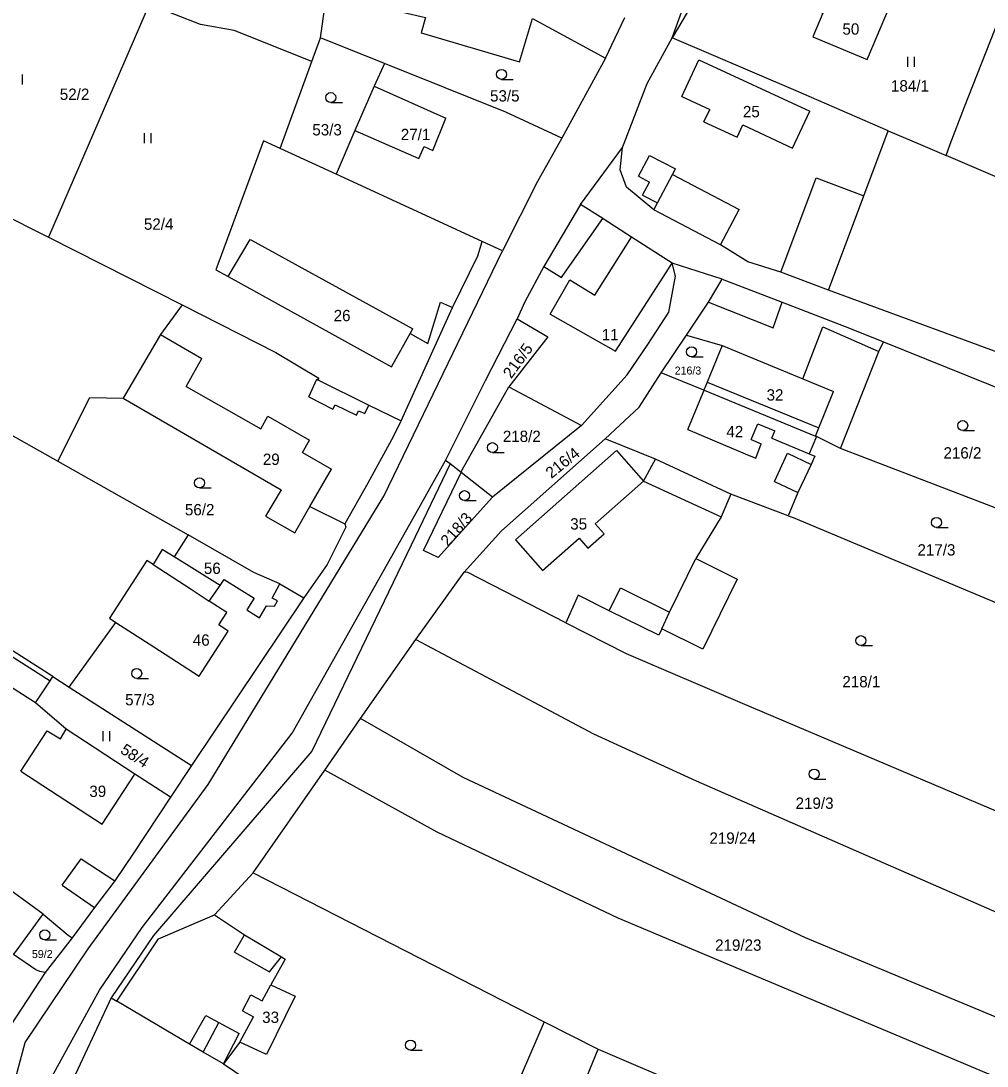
# Model space of a CAD drawing. Extents: x -744566 to -741843, y -1128407 to -1126744.
# Drawn here: x -743048.6 to -742903.8, y -1127701.7 to -1127545.1 of the extents above; entities that cross this region are included whole.
import ezdxf

# ---------------------------------------------------------------- set-up
doc = ezdxf.new("R2010")
doc.units = 0
for name, color, linetype in [('Hranice parcel', 7, 'Continuous'), ('Parcelní čísla', 7, 'Continuous'), ('Vnitřní kresba', 7, 'Continuous'), ('Značky kultur', 7, 'Continuous')]:
    doc.layers.add(name, color=color, linetype=linetype)

msp = doc.modelspace()

# ---------------------------------------------------------------- linework, layer by layer
at = {"layer": 'Hranice parcel'}
for p, q in [((-742950.97, -1127547.61), (-742944.28, -1127528.98)), ((-743029.41, -1127542.64), (-743044.5, -1127577.53)), ((-743003.69, -1127547.61), (-743002.99, -1127542.69)), ((-742960.97, -1127550.69), (-742958.07, -1127544.59)), ((-743005.01, -1127551.2), (-743003.69, -1127547.61)), ((-742994.1, -1127551.47), (-743003.69, -1127547.61)), ((-743009.74, -1127564.2), (-743005.01, -1127551.2)), ((-742960.97, -1127550.69), (-742967.51, -1127562.65)), ((-743001.38, -1127568.05), (-743009.74, -1127564.2)), ((-742964.75, -1127572.6), (-742958.43, -1127564.08)), ((-743067.95, -1127565.66), (-743044.5, -1127577.53)), ((-742979.47, -1127578.16), (-743001.38, -1127568.05)), ((-743044.5, -1127577.53), (-743024.44, -1127587.67)), ((-742943.48, -1127583.82), (-742951.01, -1127581.4)), ((-742985.72, -1127587.27), (-742983.9, -1127588.07)), ((-743082.43, -1127588.87), (-743043.08, -1127611.1)), ((-742991.6, -1127605.04), (-742983.9, -1127588.07)), ((-742952.62, -1127597.82), (-742948.85, -1127592.21)), ((-742919.33, -1127593.19), (-742889.07, -1127605.41)), ((-742946.24, -1127600.44), (-742952.62, -1127597.82)), ((-742982.46, -1127612.4), (-742975.48, -1127599.94)), ((-742975.48, -1127599.94), (-742964.56, -1127605.74)), ((-742964.56, -1127605.74), (-742977.94, -1127616.47)), ((-742925.74, -1127609.17), (-742929.36, -1127607.37)), ((-742892.31, -1127622.04), (-742925.74, -1127609.17)), ((-743043.08, -1127611.1), (-743023.57, -1127622.12)), ((-742982.64, -1127612.78), (-742984.29, -1127611.5)), ((-742982.64, -1127612.78), (-742982.46, -1127612.4)), ((-742977.94, -1127616.47), (-742982.64, -1127612.78)), ((-742933.59, -1127619.25), (-742942.21, -1127616.04)), ((-743023.57, -1127622.12), (-743025.65, -1127625.44)), ((-743029.73, -1127625.98), (-743035.35, -1127634.62)), ((-743018.73, -1127629.7), (-743025.65, -1127625.44)), ((-742989.43, -1127637.82), (-742982.16, -1127627.73)), ((-743009.79, -1127629.49), (-743006.21, -1127631.58)), ((-743006.21, -1127631.58), (-743023.07, -1127656.68)), ((-743041.39, -1127644.94), (-743034.37, -1127635.25)), ((-743035.35, -1127634.62), (-743034.37, -1127635.25)), ((-743043.83, -1127643.37), (-743054.68, -1127636.42)), ((-742997.69, -1127649.67), (-742989.43, -1127637.82)), ((-743046.41, -1127647.29), (-743053.43, -1127642.86)), ((-743043.83, -1127643.37), (-743041.39, -1127644.94)), ((-743041.39, -1127644.94), (-743023.07, -1127656.68)), ((-743003.07, -1127657.38), (-742997.69, -1127649.67)), ((-743023.07, -1127656.68), (-743026.2, -1127661.44)), ((-743013.81, -1127672.8), (-743003.07, -1127657.38)), ((-743045.29, -1127678.95), (-743062.24, -1127666.73)), ((-743019.62, -1127679.08), (-743013.81, -1127672.8)), ((-743013.81, -1127672.8), (-742970.18, -1127695.1)), ((-743040.96, -1127682.5), (-743044.97, -1127687.73)), ((-743044.97, -1127687.73), (-743050.26, -1127695.79)), ((-743035.1, -1127691.53), (-743041.92, -1127706.05)), ((-743035.1, -1127691.53), (-743034.24, -1127692.03)), ((-742970.18, -1127695.1), (-742980.63, -1127719.3)), ((-742970.18, -1127695.1), (-742962.09, -1127699.23)), ((-742972.01, -1127723.11), (-742962.09, -1127699.23)), ((-742962.09, -1127699.23), (-742911.19, -1127720.85))]:
    msp.add_line(p, q, dxfattribs=at)
for points in [[(-742942.64, -1127536.81), (-742945.7, -1127538.65), (-742950.97, -1127547.61)], [(-742925.16, -1127536.21), (-742926.91, -1127540.37), (-742928.31, -1127539.78), (-742929.81, -1127543.36), (-742928.41, -1127543.95), (-742929.89, -1127547.48), (-742921.76, -1127550.89), (-742917.03, -1127539.62), (-742925.16, -1127536.21)], [(-743005.01, -1127551.2), (-743016.66, -1127546.56), (-743021.68, -1127545.63), (-743029.41, -1127542.64)], [(-743002.99, -1127542.69), (-742991.4, -1127543.81), (-742987.95, -1127544.57), (-742988.63, -1127546.87), (-742973.89, -1127551.23), (-742971.94, -1127544.76), (-742960.97, -1127550.69)], [(-742909.93, -1127565.28), (-742909.31, -1127563.59), (-742907.18, -1127557.98), (-742901.31, -1127543.14)], [(-742958.43, -1127564.08), (-742954.72, -1127554.49), (-742950.97, -1127547.61)], [(-742918.6, -1127561.55), (-742932.41, -1127555.57), (-742950.97, -1127547.61)], [(-742994.1, -1127551.47), (-742995.64, -1127554.9), (-742998.58, -1127561.51), (-743001.38, -1127568.05)], [(-742967.51, -1127562.65), (-742975.9, -1127558.78), (-742994.1, -1127551.47)], [(-742927.53, -1127585.44), (-742922.25, -1127571.32), (-742918.6, -1127561.55)], [(-742918.6, -1127561.55), (-742913.78, -1127563.64), (-742909.93, -1127565.28)], [(-743009.74, -1127564.2), (-743012.24, -1127563.05), (-743019.38, -1127582.4), (-743017.56, -1127583.41), (-742993.08, -1127596.96), (-742990.26, -1127591.96)], [(-742967.51, -1127562.65), (-742971.19, -1127569.17), (-742976.43, -1127579.56), (-742979.47, -1127578.16)], [(-742927.53, -1127585.44), (-742934.7, -1127582.76), (-742939.64, -1127581.23), (-742943.72, -1127578.66), (-742953.72, -1127573.43), (-742957.84, -1127570.04), (-742958.76, -1127567.42), (-742958.43, -1127564.08)], [(-742851.05, -1127590.28), (-742889.01, -1127574.21), (-742909.93, -1127565.28)], [(-742964.75, -1127572.6), (-742970.21, -1127581.92), (-742973.05, -1127587.2), (-742974.2, -1127589.77)], [(-742951.01, -1127581.4), (-742957.06, -1127577.5), (-742961.32, -1127574.78), (-742961.39, -1127574.71), (-742964.75, -1127572.6)], [(-742983.9, -1127588.07), (-742980.12, -1127580.33), (-742979.47, -1127578.16)], [(-742964.56, -1127605.74), (-742957.73, -1127598.16), (-742954.62, -1127593.61), (-742951.47, -1127588.73), (-742950.51, -1127583.33), (-742951.01, -1127581.4)], [(-742948.85, -1127592.21), (-742945.53, -1127587.26), (-742943.48, -1127583.82)], [(-742943.48, -1127583.82), (-742934.51, -1127587.27), (-742924.42, -1127591.13), (-742919.33, -1127593.19)], [(-742885.79, -1127600.64), (-742896.8, -1127596.74), (-742927.53, -1127585.44)], [(-742990.26, -1127591.96), (-742987.63, -1127593.44), (-742985.72, -1127587.27)], [(-743024.44, -1127587.67), (-743027.7, -1127592.11), (-743033.28, -1127601.65)], [(-743024.44, -1127587.67), (-743010.42, -1127594.79), (-743003.98, -1127598.66), (-743004.09, -1127598.89), (-742996.47, -1127602.7), (-742991.6, -1127605.04)], [(-742984.29, -1127611.5), (-742984.97, -1127610.98), (-742978.95, -1127598.97), (-742974.2, -1127589.77)], [(-742974.2, -1127589.77), (-742969.61, -1127592.47), (-742975.48, -1127599.94)], [(-742948.85, -1127592.21), (-742943.5, -1127593.76), (-742945.74, -1127599.22), (-742946.24, -1127600.44)], [(-742925.74, -1127609.17), (-742920.01, -1127594.66), (-742919.33, -1127593.19)], [(-742961.05, -1127607.72), (-742955.92, -1127602.99), (-742952.62, -1127597.82)], [(-742946.24, -1127600.44), (-742946.19, -1127600.46), (-742929.52, -1127607.31), (-742929.36, -1127607.37)], [(-743043.08, -1127611.1), (-743038.28, -1127601.54), (-743033.28, -1127601.65)], [(-743033.28, -1127601.65), (-743009.6, -1127615.39), (-743011.96, -1127619.34), (-743007.55, -1127621.8), (-743005.29, -1127617.87), (-743000.05, -1127620.45)], [(-742991.6, -1127605.04), (-742993.07, -1127607.9), (-742996.62, -1127614.4), (-743000.05, -1127620.45)], [(-742929.36, -1127607.37), (-742930.45, -1127609.97), (-742929.58, -1127610.33), (-742930.16, -1127611.56), (-742932.13, -1127615.77), (-742933.59, -1127619.25)], [(-742982.16, -1127627.73), (-742976.55, -1127621.53), (-742961.05, -1127607.72)], [(-742942.21, -1127616.04), (-742953.51, -1127610.79), (-742961.05, -1127607.72)], [(-742984.29, -1127611.5), (-742990.11, -1127623.65), (-743005.02, -1127654.54), (-743028.72, -1127682.17), (-743035.1, -1127691.53)], [(-742977.94, -1127616.47), (-742986.05, -1127625.51), (-742988.28, -1127624.48), (-742982.64, -1127612.78)], [(-742942.21, -1127616.04), (-742943.64, -1127619.44), (-742947.46, -1127625.69), (-742941.23, -1127628.77), (-742946.4, -1127639.24), (-742952.54, -1127636.21), (-742953.01, -1127637.17), (-742960.41, -1127633.52), (-742965.09, -1127631.14), (-742966.93, -1127635.29)], [(-742933.59, -1127619.25), (-742932.84, -1127619.53), (-742895.2, -1127635.33)], [(-743000.05, -1127620.45), (-742999.93, -1127620.98), (-743002.72, -1127626.56), (-743006.21, -1127631.58)], [(-743009.79, -1127629.49), (-743013.72, -1127627.78), (-743023.57, -1127622.12)], [(-743025.65, -1127625.44), (-743027.43, -1127624.34), (-743028.79, -1127626.59), (-743029.73, -1127625.98)], [(-742966.93, -1127635.29), (-742981.61, -1127627.78), (-742982.16, -1127627.73)], [(-743018.73, -1127629.7), (-743018.16, -1127628.82), (-743013.67, -1127631.63), (-743014.75, -1127633.35), (-743012.87, -1127634.54), (-743011.82, -1127632.78), (-743010.61, -1127632.81), (-743010.16, -1127632.03), (-743010.94, -1127631.59), (-743009.79, -1127629.49)], [(-743034.37, -1127635.25), (-743028.68, -1127638.9), (-743021.92, -1127643.29), (-743017.55, -1127636.55), (-743018.97, -1127635.6), (-743017.73, -1127633.76), (-743020.38, -1127632.04), (-743018.73, -1127629.7)], [(-742966.93, -1127635.29), (-742957.86, -1127639.93), (-742940.86, -1127647.2), (-742894.92, -1127666.66), (-742890.34, -1127668.53)], [(-742989.43, -1127637.82), (-742962.79, -1127651.94), (-742947.37, -1127659.01), (-742888.66, -1127684.65), (-742875.08, -1127689.31), (-742869.86, -1127690.69)], [(-743046.41, -1127647.29), (-743044.24, -1127643.99), (-743043.83, -1127643.37)], [(-743026.2, -1127661.44), (-743031.54, -1127657.97), (-743041.85, -1127651.26), (-743046.41, -1127647.29)], [(-742884.93, -1127701.69), (-742931.01, -1127682.52), (-742982.33, -1127658.51), (-742997.69, -1127649.67)], [(-742892.82, -1127707.45), (-742959.07, -1127679.57), (-742986.2, -1127666.67), (-743003.07, -1127657.38)], [(-743026.2, -1127661.44), (-743031.72, -1127669.85), (-743034.56, -1127673.98), (-743037.58, -1127678), (-743040.96, -1127682.5)], [(-743044.97, -1127687.73), (-743045.79, -1127687.59), (-743046.39, -1127687.31), (-743049.72, -1127685.03), (-743049.19, -1127684.3), (-743045.58, -1127679.36), (-743045.29, -1127678.95)], [(-743045.29, -1127678.95), (-743041.53, -1127682.11), (-743040.96, -1127682.5)], [(-743034.24, -1127692.03), (-743027.99, -1127682.66), (-743019.62, -1127679.08)], [(-743019.62, -1127679.08), (-743015.08, -1127682.06), (-743009.56, -1127685.38), (-743009, -1127685.72), (-743011.13, -1127689.55), (-743007.52, -1127691.27), (-743011.82, -1127700.03), (-743015.78, -1127698.17), (-743018.27, -1127701.4)], [(-743018.27, -1127701.4), (-743021.3, -1127699.65), (-743023.34, -1127698.47), (-743034.24, -1127692.03)], [(-743018.27, -1127701.4), (-743013, -1127704.97), (-742980.63, -1127719.3)]]:
    msp.add_lwpolyline(points, dxfattribs=at)
at = {"layer": 'Vnitřní kresba'}
for p, q in [((-742949.53, -1127556.44), (-742946.97, -1127550.91)), ((-742946.97, -1127550.91), (-742930.37, -1127558.61)), ((-742995.64, -1127554.9), (-742984.94, -1127559.69)), ((-742949.53, -1127556.44), (-742945.36, -1127558.38)), ((-742946.22, -1127560.22), (-742945.36, -1127558.38)), ((-742932.94, -1127564.15), (-742930.37, -1127558.61)), ((-742986.89, -1127564.52), (-742984.94, -1127559.69)), ((-742946.22, -1127560.22), (-742941.23, -1127562.53)), ((-742998.58, -1127561.51), (-742988.98, -1127565.74)), ((-742941.23, -1127562.53), (-742940.37, -1127560.69)), ((-742940.37, -1127560.69), (-742932.94, -1127564.15)), ((-742988.98, -1127565.74), (-742988.19, -1127563.94)), ((-742988.19, -1127563.94), (-742986.89, -1127564.52)), ((-742956.04, -1127568.39), (-742954.4, -1127565.26)), ((-742954.4, -1127565.26), (-742950.51, -1127567.29)), ((-742956.04, -1127568.39), (-742954.4, -1127569.25)), ((-742953.17, -1127572.37), (-742950.95, -1127568.13)), ((-742950.95, -1127568.13), (-742950.51, -1127567.29)), ((-742950.95, -1127568.13), (-742940.95, -1127573.36)), ((-742955.42, -1127571.19), (-742954.4, -1127569.25)), ((-742934.7, -1127582.76), (-742929.42, -1127568.64)), ((-742929.42, -1127568.64), (-742922.25, -1127571.32)), ((-742955.42, -1127571.19), (-742953.17, -1127572.37)), ((-742953.72, -1127573.43), (-742953.17, -1127572.37)), ((-742967.39, -1127583.25), (-742961.39, -1127574.71)), ((-742943.72, -1127578.66), (-742940.95, -1127573.36)), ((-743017.56, -1127583.41), (-743014.23, -1127577.87)), ((-743014.23, -1127577.87), (-743014.05, -1127577.97)), ((-742962.56, -1127586.21), (-742957.06, -1127577.5)), ((-743014.05, -1127577.97), (-742989.86, -1127591.25)), ((-742994.19, -1127616.32), (-742976.43, -1127579.56)), ((-742970.21, -1127581.92), (-742967.6, -1127583.54)), ((-742959.5, -1127594.6), (-742951.01, -1127581.4)), ((-742969.28, -1127589.06), (-742966.31, -1127583.91)), ((-742967.6, -1127583.54), (-742967.39, -1127583.25)), ((-742966.31, -1127583.91), (-742962.56, -1127586.21)), ((-742945.53, -1127587.26), (-742935.86, -1127591.09)), ((-742935.86, -1127591.09), (-742934.51, -1127587.27)), ((-742969.28, -1127589.06), (-742959.5, -1127594.6)), ((-742990.26, -1127591.96), (-742989.86, -1127591.25)), ((-742931.41, -1127598.72), (-742928.39, -1127590.97)), ((-742928.39, -1127590.97), (-742920.01, -1127594.66)), ((-743027.7, -1127592.11), (-743021.5, -1127595.7)), ((-742943.5, -1127593.76), (-742931.41, -1127598.72)), ((-743023.86, -1127599.87), (-743021.5, -1127595.7)), ((-743005.46, -1127601.43), (-743004.27, -1127598.8)), ((-743004.27, -1127598.8), (-743004.09, -1127598.89)), ((-742945.74, -1127599.22), (-742929.02, -1127606.08)), ((-742931.41, -1127598.72), (-742926.78, -1127600.62)), ((-743023.86, -1127599.87), (-743012.63, -1127606.25)), ((-742948.66, -1127606.36), (-742946.33, -1127600.8)), ((-742946.33, -1127600.8), (-742946.19, -1127600.46)), ((-742929.02, -1127606.08), (-742926.78, -1127600.62)), ((-743005.46, -1127601.43), (-743001.84, -1127603.28)), ((-743001.84, -1127603.28), (-743001.52, -1127602.66)), ((-743001.52, -1127602.66), (-742998.3, -1127604.18)), ((-742997.05, -1127603.92), (-742996.47, -1127602.7)), ((-743012.63, -1127606.25), (-743011.59, -1127604.36)), ((-743011.59, -1127604.36), (-743005.38, -1127607.91)), ((-742998.3, -1127604.18), (-742997.99, -1127603.52)), ((-742997.99, -1127603.52), (-742997.05, -1127603.92)), ((-742939.14, -1127607.84), (-742938.15, -1127605.48)), ((-742938.15, -1127605.48), (-742935.61, -1127606.55)), ((-742929.52, -1127607.31), (-742929.02, -1127606.08)), ((-742948.66, -1127606.36), (-742940.04, -1127609.97)), ((-742936.05, -1127607.62), (-742935.61, -1127606.55)), ((-742936.05, -1127607.62), (-742930.45, -1127609.97)), ((-743006.43, -1127609.77), (-743005.38, -1127607.91)), ((-742939.14, -1127607.84), (-742937.66, -1127608.47)), ((-742938.46, -1127610.63), (-742937.66, -1127608.47)), ((-743006.43, -1127609.77), (-743002.05, -1127612.26)), ((-742974.48, -1127622.89), (-742959.34, -1127609.47)), ((-742959.34, -1127609.47), (-742955.28, -1127614.06)), ((-742953.75, -1127611.23), (-742953.51, -1127610.79)), ((-742940.04, -1127609.97), (-742938.46, -1127610.63)), ((-742935.66, -1127614.11), (-742933.69, -1127609.9)), ((-742933.69, -1127609.9), (-742930.16, -1127611.56)), ((-743005.29, -1127617.87), (-743002.05, -1127612.26)), ((-742989.42, -1127618.93), (-742984.97, -1127610.98)), ((-742955.28, -1127614.06), (-742953.75, -1127611.23)), ((-742962.53, -1127620.48), (-742955.28, -1127614.06)), ((-742955.28, -1127614.06), (-742943.64, -1127619.44)), ((-742935.66, -1127614.11), (-742932.13, -1127615.77)), ((-743020.57, -1127659.55), (-742994.19, -1127616.32)), ((-743007.93, -1127651.85), (-742989.42, -1127618.93)), ((-742962.53, -1127620.48), (-742961.2, -1127621.98)), ((-742974.48, -1127622.89), (-742970.42, -1127627.47)), ((-742970.42, -1127627.47), (-742964.95, -1127622.62)), ((-742964.95, -1127622.62), (-742963.62, -1127624.12)), ((-742963.62, -1127624.12), (-742961.2, -1127621.98)), ((-742951.41, -1127633.7), (-742947.46, -1127625.69)), ((-743028.79, -1127626.59), (-743023.09, -1127630.28)), ((-743023.09, -1127630.28), (-743020.38, -1127632.04)), ((-742960.41, -1127633.52), (-742958.72, -1127630.09)), ((-742958.72, -1127630.09), (-742951.41, -1127633.7)), ((-742952.54, -1127636.21), (-742951.41, -1127633.7)), ((-743055.09, -1127637.08), (-743044.24, -1127643.99)), ((-743048.61, -1127657.52), (-743044.69, -1127651.52)), ((-743044.69, -1127651.52), (-743042.7, -1127652.7)), ((-743042.7, -1127652.7), (-743041.85, -1127651.26)), ((-743030.45, -1127680.95), (-743007.93, -1127651.85)), ((-743048.61, -1127657.52), (-743036.42, -1127665.5)), ((-743036.42, -1127665.5), (-743031.54, -1127657.97)), ((-743038.55, -1127684.18), (-743020.57, -1127659.55)), ((-743042.45, -1127674.62), (-743039.6, -1127670.68)), ((-743039.6, -1127670.68), (-743034.56, -1127673.98)), ((-743042.45, -1127674.62), (-743037.58, -1127678)), ((-743036.85, -1127690.37), (-743030.45, -1127680.95)), ((-743016.62, -1127684.69), (-743015.08, -1127682.06)), ((-743047.98, -1127698.19), (-743038.55, -1127684.18)), ((-743016.62, -1127684.69), (-743011.36, -1127687.63)), ((-743011.36, -1127687.63), (-743009.56, -1127685.38)), ((-743044.25, -1127703.82), (-743036.85, -1127690.37)), ((-743012.44, -1127691.97), (-743011.13, -1127689.55)), ((-743015.4, -1127693.46), (-743014.15, -1127691.05)), ((-743014.15, -1127691.05), (-743012.44, -1127691.97)), ((-743015.4, -1127693.46), (-743013.73, -1127694.36)), ((-743023.34, -1127698.47), (-743020.92, -1127694.17)), ((-743021.3, -1127699.65), (-743018.97, -1127695.22)), ((-743020.92, -1127694.17), (-743018.97, -1127695.22)), ((-743018.97, -1127695.22), (-743015.9, -1127696.88)), ((-743015.78, -1127698.17), (-743013.73, -1127694.36)), ((-743018.27, -1127701.4), (-743015.9, -1127696.88)), ((-743050.88, -1127709.04), (-743047.98, -1127698.19))]:
    msp.add_line(p, q, dxfattribs=at)
at = {"layer": 'Značky kultur'}
for p, q in [((-742915.641, -1127551.98), (-742915.641, -1127550.48)), ((-742914.64, -1127551.98), (-742914.64, -1127550.48)), ((-743048.37, -1127554.65), (-743048.37, -1127553.15)), ((-742976.573, -1127553.86), (-742974.823, -1127553.86)), ((-743002.173, -1127557.34), (-743000.423, -1127557.34)), ((-743030.071, -1127563.43), (-743030.071, -1127561.93)), ((-743029.07, -1127563.43), (-743029.07, -1127561.93)), ((-742948.083, -1127595.45), (-742946.333, -1127595.45)), ((-742907.433, -1127606.5), (-742905.683, -1127606.5)), ((-742977.933, -1127609.8), (-742976.183, -1127609.8)), ((-743021.843, -1127615.09), (-743020.093, -1127615.09)), ((-742982.113, -1127617), (-742980.363, -1127617)), ((-742911.363, -1127621.01), (-742909.613, -1127621.01)), ((-742922.693, -1127638.73), (-742920.943, -1127638.73)), ((-743031.263, -1127643.64), (-743029.513, -1127643.64)), ((-743036.311, -1127653.07), (-743036.311, -1127651.57)), ((-743035.31, -1127653.07), (-743035.31, -1127651.57)), ((-742929.703, -1127658.72), (-742927.953, -1127658.72)), ((-743045.033, -1127682.83), (-743043.283, -1127682.83)), ((-742990.213, -1127699.35), (-742988.463, -1127699.35))]:
    msp.add_line(p, q, dxfattribs=at)
for centre in [(-742976.573, -1127553.11), (-743002.173, -1127556.59), (-742948.083, -1127594.7), (-742907.433, -1127605.75), (-742977.933, -1127609.05), (-743021.843, -1127614.34), (-742982.113, -1127616.25), (-742911.363, -1127620.26), (-742922.693, -1127637.98), (-743031.263, -1127642.89), (-742929.703, -1127657.97), (-743045.033, -1127682.08), (-742990.213, -1127698.6)]:
    msp.add_circle(centre, 0.75, dxfattribs=at)

# ---------------------------------------------------------------- texts
at = {"layer": 'Parcelní čísla'}
for s, height, p in [('50', 1.7, (-742925.462, -1127547.16)), ('184/1', 1.7, (-742918.183, -1127555.68)), ('52/2', 1.7, (-743042.79, -1127556.94)), ('53/5', 1.7, (-742978.291, -1127557.18)), ('25', 1.7, (-742940.382, -1127559.54)), ('53/3', 1.7, (-743004.931, -1127562.26)), ('27/1', 1.7, (-742991.671, -1127562.97)), ('52/4', 1.7, (-743030.18, -1127576.4)), ('26', 1.7, (-743001.732, -1127590.11)), ('11', 1.7, (-742961.552, -1127592.98)), ('216/3', 1.19, (-742950.611, -1127598.095)), ('32', 1.7, (-742936.832, -1127602)), ('42', 1.7, (-742942.862, -1127607.5)), ('218/2', 1.7, (-742976.373, -1127608.21)), ('216/2', 1.7, (-742910.313, -1127610.69)), ('29', 1.7, (-743012.352, -1127611.65)), ('56/2', 1.7, (-743024.031, -1127619.2)), ('35', 1.7, (-742966.272, -1127621.33)), ('217/3', 1.7, (-742914.213, -1127625.23)), ('56', 1.7, (-743021.192, -1127627.98)), ('46', 1.7, (-743022.852, -1127638.74)), ('218/1', 1.7, (-742925.473, -1127644.98)), ('57/3', 1.7, (-743032.991, -1127647.67)), ('39', 1.7, (-743038.362, -1127661.41)), ('219/3', 1.7, (-742932.483, -1127663.19)), ('219/24', 1.7, (-742945.4, -1127668.42)), ('219/23', 1.7, (-742944.55, -1127684.46)), ('59/2', 1.19, (-743046.968, -1127685.545)), ('33', 1.7, (-743012.452, -1127695.28))]:
    msp.add_text(s, height=height, dxfattribs=at).set_placement(p)
for s, rotation, p in [('216/5', 54, (-742975.112, -1127598.819)), ('216/4', 39, (-742969.09, -1127613.765)), ('218/3', 48, (-742984.618, -1127623.958)), ('58/4', 327, (-743033.842, -1127654.732))]:
    msp.add_text(s, height=1.7, rotation=rotation, dxfattribs=at).set_placement(p)

doc.saveas('drawing.dxf')
